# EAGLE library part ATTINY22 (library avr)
MICROCONTROLLER 1K ROM 128 bytes RAM 128 bytes EEPROM
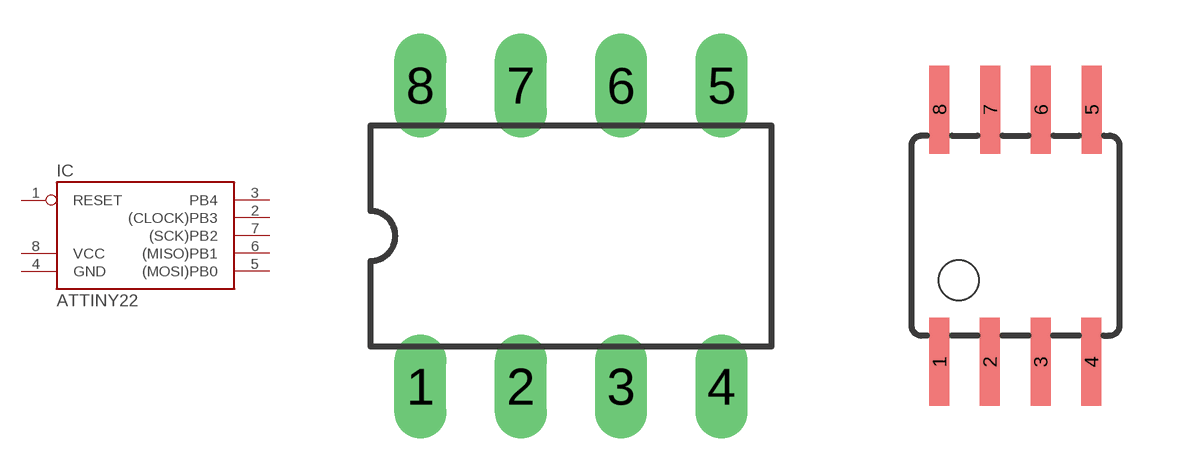
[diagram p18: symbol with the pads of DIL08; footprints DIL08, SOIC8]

Designator prefix IC

## ATTINY22P  [DIL08]
1  RESET  in
2  (CLOCK)PB3
3  PB4
4  GND  pwr
5  (MOSI)PB0
6  (MISO)PB1
7  (SCK)PB2
8  VCC  pwr

## ATTINY22S  [SOIC8]
Pads as for DIL08

## Footprint DIL08 (pad centres in mm)
Dual In Line
drill 0.813 long: 1 -3.81,-3.81; 2 -1.27,-3.81; 3 1.27,-3.81; 4 3.81,-3.81; 5 3.81,3.81; 6 1.27,3.81; 7 -1.27,3.81; 8 -3.81,3.81

## Footprint SOIC8 (pad centres in mm)
Wide Plastic Gull Wing Small Outline Package
smd 0.5 x 2.2: 1 -1.905,-3.154; 2 -0.645,-3.154; 3 0.625,-3.154; 4 1.895,-3.154; 5 1.905,3.154; 6 0.635,3.154; 7 -0.635,3.154; 8 -1.905,3.154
